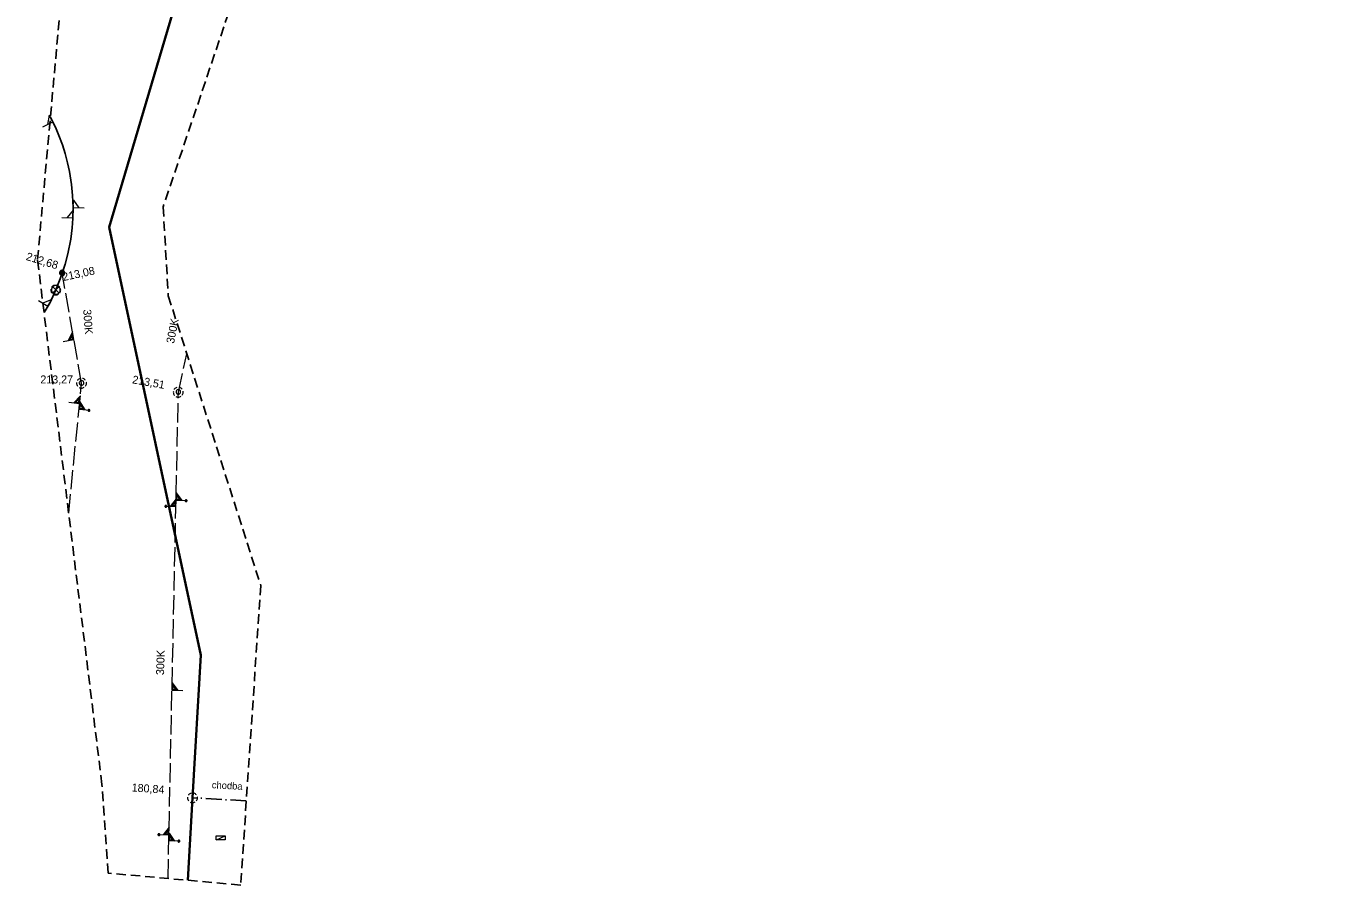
# Model space of a CAD drawing. Extents: x -744446 to -743929, y -1041261 to -1040599.
# Drawn here: x -744446.3 to -744316.9, y -1041260.9 to -1041175.1 of the extents above; entities that cross this region are included whole.
import ezdxf

# ---------------------------------------------------------------- set-up
doc = ezdxf.new("R2010")
doc.units = 0
doc.header["$LTSCALE"] = 0.32
for name, pattern in [('DOT_DASHED', [7.7, 5, -1.2, 0.3, -1.2]), ('LONG_DASHED', [7.5, 6, -1.5]), ('MEDIUM_DASHED', [4.5, 3, -1.5])]:
    doc.linetypes.add(name, pattern=pattern)
for name, color, linetype, lineweight in [('1', 7, 'MEDIUM_DASHED', 25), ('18', 7, 'Continuous', 13), ('20', 7, 'LONG_DASHED', 13)]:
    doc.layers.add(name, color=color, linetype=linetype, lineweight=lineweight)

msp = doc.modelspace()

# ---------------------------------------------------------------- linework, layer by layer
at = {"layer": '1'}
msp.add_lwpolyline([(-744438.077, -1041259.731), (-744438.679, -1041250.888), (-744445.125, -1041198.426), (-744434.434, -1041080.103), (-744426.87, -1040938.41), (-744425.446, -1040859.072), (-744414.192, -1040822.094), (-744390.076, -1040771.45), (-744357.118, -1040726.434), (-744307.278, -1040693.475), (-744241.36, -1040670.967), (-743937.498, -1040598.618), (-743928.655, -1040619.519), (-744129.684, -1040665.585), (-744218.109, -1040687.29), (-744311.358, -1040718.641), (-744361.198, -1040777.323), (-744391.745, -1040864.141), (-744411.355, -1041059.185), (-744416.379, -1041145.154), (-744432.569, -1041193.163), (-744432.047, -1041202.053), (-744422.803, -1041230.992), (-744424.813, -1041260.936)], close=True, dxfattribs=at)
at = {"layer": '18'}
for p, q in [((-744442.984, -1041201.759), (-744443.602, -1041201.141)), ((-744443.602, -1041201.759), (-744442.985, -1041201.142)), ((-744427.244, -1041256.421), (-744426.37, -1041256.009))]:
    msp.add_line(p, q, dxfattribs=at)
at = {"layer": '18', "linetype": 'DOT_DASHED', "lineweight": 25}
msp.add_line((-744424.248, -1041252.521), (-744429.62, -1041252.21), dxfattribs=at)
at = {"layer": '18'}
for points in [[(-744444.601, -1041185.157), (-744443.607, -1041184.656), (-744443.949, -1041183.978), (-744444.136, -1041184.924)], [(-744440.468, -1041193.273), (-744441.565, -1041193.244), (-744441.545, -1041192.471), (-744440.988, -1041193.259)], [(-744442.696, -1041194.214), (-744441.583, -1041194.243), (-744441.563, -1041193.483), (-744442.176, -1041194.228)], [(-744443.445, -1041200.988), (-744443.516, -1041201.016), (-744443.583, -1041201.055), (-744443.643, -1041201.103), (-744443.694, -1041201.16), (-744443.718, -1041201.194)], [(-744442.904, -1041201.171), (-744442.954, -1041201.113), (-744443.012, -1041201.063), (-744443.077, -1041201.022), (-744443.148, -1041200.993), (-744443.197, -1041200.979)], [(-744445.036, -1041202.494), (-744444.082, -1041203.068), (-744443.691, -1041202.416), (-744444.591, -1041202.763)], [(-744443.79, -1041201.38), (-744443.796, -1041201.457), (-744443.791, -1041201.534), (-744443.774, -1041201.609), (-744443.745, -1041201.68), (-744443.705, -1041201.746), (-744443.689, -1041201.768)], [(-744443.532, -1041201.897), (-744443.462, -1041201.928), (-744443.387, -1041201.947), (-744443.311, -1041201.954), (-744443.234, -1041201.949), (-744443.159, -1041201.932), (-744443.087, -1041201.904), (-744443.027, -1041201.869)], [(-744442.909, -1041201.757), (-744442.868, -1041201.692), (-744442.837, -1041201.622), (-744442.818, -1041201.547), (-744442.81, -1041201.471), (-744442.815, -1041201.394), (-744442.821, -1041201.359)], [(-744442.565, -1041206.597), (-744441.486, -1041206.406), (-744441.62, -1041205.647), (-744442.055, -1041206.507)], [(-744441.948, -1041206.436), (-744441.538, -1041206.364), (-744441.636, -1041205.807), (-744441.949, -1041206.436)], [(-744441.873, -1041206.375), (-744441.587, -1041206.324), (-744441.651, -1041205.959), (-744441.873, -1041206.376)], [(-744441.217, -1041210.69), (-744441.223, -1041210.767), (-744441.218, -1041210.844), (-744441.201, -1041210.919), (-744441.172, -1041210.99), (-744441.132, -1041211.056), (-744441.116, -1041211.078)], [(-744440.872, -1041210.298), (-744440.943, -1041210.326), (-744441.01, -1041210.365), (-744441.07, -1041210.413), (-744441.121, -1041210.47), (-744441.145, -1041210.504)], [(-744440.959, -1041211.207), (-744440.889, -1041211.238), (-744440.814, -1041211.257), (-744440.738, -1041211.264), (-744440.661, -1041211.259), (-744440.586, -1041211.242), (-744440.514, -1041211.214), (-744440.454, -1041211.179)], [(-744440.331, -1041210.481), (-744440.381, -1041210.423), (-744440.439, -1041210.373), (-744440.504, -1041210.332), (-744440.575, -1041210.303), (-744440.624, -1041210.289)], [(-744440.336, -1041211.067), (-744440.295, -1041211.002), (-744440.264, -1041210.932), (-744440.245, -1041210.857), (-744440.237, -1041210.781), (-744440.242, -1041210.704), (-744440.248, -1041210.669)], [(-744431.198, -1041211.2), (-744431.269, -1041211.228), (-744431.336, -1041211.267), (-744431.396, -1041211.315), (-744431.447, -1041211.372), (-744431.471, -1041211.406)], [(-744430.657, -1041211.383), (-744430.707, -1041211.325), (-744430.765, -1041211.275), (-744430.83, -1041211.234), (-744430.901, -1041211.205), (-744430.95, -1041211.191)], [(-744442.008, -1041212.686), (-744440.918, -1041212.795), (-744440.841, -1041212.028), (-744441.493, -1041212.738)], [(-744441.37, -1041212.699), (-744440.956, -1041212.74), (-744440.9, -1041212.177), (-744441.371, -1041212.698)], [(-744441.282, -1041212.66), (-744440.993, -1041212.689), (-744440.956, -1041212.32), (-744441.282, -1041212.661)], [(-744439.885, -1041213.504), (-744440.975, -1041213.396), (-744440.899, -1041212.63), (-744440.4, -1041213.453)], [(-744440.512, -1041213.392), (-744440.926, -1041213.351), (-744440.87, -1041212.787), (-744440.511, -1041213.392)], [(-744431.543, -1041211.592), (-744431.549, -1041211.669), (-744431.544, -1041211.746), (-744431.527, -1041211.821), (-744431.498, -1041211.892), (-744431.458, -1041211.958), (-744431.442, -1041211.98)], [(-744431.285, -1041212.109), (-744431.215, -1041212.14), (-744431.14, -1041212.159), (-744431.064, -1041212.166), (-744430.987, -1041212.161), (-744430.912, -1041212.144), (-744430.84, -1041212.116), (-744430.78, -1041212.081)], [(-744430.662, -1041211.969), (-744430.621, -1041211.904), (-744430.59, -1041211.834), (-744430.571, -1041211.759), (-744430.563, -1041211.683), (-744430.568, -1041211.606), (-744430.574, -1041211.571)], [(-744440.591, -1041213.337), (-744440.882, -1041213.308), (-744440.845, -1041212.938), (-744440.591, -1041213.338)], [(-744430.175, -1041222.525), (-744431.27, -1041222.502), (-744431.254, -1041221.732), (-744430.692, -1041222.514)], [(-744430.809, -1041222.461), (-744431.225, -1041222.453), (-744431.213, -1041221.887), (-744430.808, -1041222.461)], [(-744432.384, -1041223.076), (-744431.289, -1041223.099), (-744431.273, -1041222.329), (-744431.867, -1041223.087)], [(-744431.747, -1041223.039), (-744431.331, -1041223.048), (-744431.319, -1041222.482), (-744431.749, -1041223.039)], [(-744431.663, -1041222.993), (-744431.371, -1041223), (-744431.363, -1041222.629), (-744431.663, -1041222.994)], [(-744430.892, -1041222.413), (-744431.184, -1041222.406), (-744431.176, -1041222.034), (-744430.892, -1041222.414)], [(-744430.583, -1041241.505), (-744431.679, -1041241.481), (-744431.663, -1041240.712), (-744431.101, -1041241.494)], [(-744431.218, -1041241.441), (-744431.634, -1041241.432), (-744431.622, -1041240.867), (-744431.217, -1041241.441)], [(-744431.301, -1041241.393), (-744431.592, -1041241.386), (-744431.584, -1041241.014), (-744431.301, -1041241.394)], [(-744430.118, -1041252.139), (-744430.124, -1041252.216), (-744430.119, -1041252.293), (-744430.102, -1041252.368), (-744430.073, -1041252.439), (-744430.032, -1041252.505), (-744430.017, -1041252.527)], [(-744429.773, -1041251.747), (-744429.844, -1041251.775), (-744429.911, -1041251.814), (-744429.971, -1041251.862), (-744430.022, -1041251.919), (-744430.046, -1041251.953)], [(-744429.86, -1041252.656), (-744429.79, -1041252.687), (-744429.715, -1041252.706), (-744429.639, -1041252.713), (-744429.562, -1041252.708), (-744429.487, -1041252.691), (-744429.415, -1041252.663), (-744429.355, -1041252.628)], [(-744429.232, -1041251.93), (-744429.282, -1041251.872), (-744429.34, -1041251.822), (-744429.405, -1041251.781), (-744429.476, -1041251.752), (-744429.525, -1041251.738)], [(-744429.237, -1041252.516), (-744429.196, -1041252.451), (-744429.165, -1041252.381), (-744429.146, -1041252.306), (-744429.138, -1041252.23), (-744429.143, -1041252.153), (-744429.149, -1041252.118)], [(-744433.082, -1041255.892), (-744431.987, -1041255.915), (-744431.971, -1041255.145), (-744432.565, -1041255.903)], [(-744432.445, -1041255.855), (-744432.029, -1041255.864), (-744432.017, -1041255.298), (-744432.447, -1041255.855)], [(-744432.361, -1041255.809), (-744432.069, -1041255.816), (-744432.061, -1041255.445), (-744432.361, -1041255.81)], [(-744430.898, -1041256.541), (-744431.993, -1041256.518), (-744431.977, -1041255.748), (-744431.415, -1041256.53)], [(-744431.532, -1041256.477), (-744431.948, -1041256.469), (-744431.936, -1041255.903), (-744431.531, -1041256.477)], [(-744431.615, -1041256.429), (-744431.907, -1041256.422), (-744431.899, -1041256.05), (-744431.615, -1041256.43)]]:
    msp.add_lwpolyline(points, dxfattribs=at)
for points in [[(-744442.4, -1041199.751), (-744442.406, -1041199.695), (-744442.423, -1041199.642), (-744442.451, -1041199.593), (-744442.49, -1041199.552), (-744442.536, -1041199.52), (-744442.588, -1041199.498), (-744442.643, -1041199.487), (-744442.699, -1041199.489), (-744442.754, -1041199.502), (-744442.804, -1041199.527), (-744442.849, -1041199.562), (-744442.885, -1041199.605), (-744442.91, -1041199.655), (-744442.925, -1041199.71), (-744442.928, -1041199.766), (-744442.919, -1041199.821), (-744442.898, -1041199.874), (-744442.867, -1041199.92), (-744442.826, -1041199.959), (-744442.779, -1041199.989), (-744442.726, -1041200.008), (-744442.67, -1041200.015), (-744442.614, -1041200.011), (-744442.559, -1041199.994), (-744442.511, -1041199.967), (-744442.469, -1041199.929), (-744442.436, -1041199.884), (-744442.413, -1041199.833), (-744442.401, -1041199.778)], [(-744442.459, -1041199.754), (-744442.465, -1041199.705), (-744442.483, -1041199.659), (-744442.511, -1041199.618), (-744442.548, -1041199.585), (-744442.592, -1041199.563), (-744442.64, -1041199.551), (-744442.689, -1041199.551), (-744442.737, -1041199.563), (-744442.781, -1041199.586), (-744442.818, -1041199.619), (-744442.846, -1041199.66), (-744442.863, -1041199.707), (-744442.869, -1041199.756), (-744442.862, -1041199.805), (-744442.844, -1041199.851), (-744442.816, -1041199.891), (-744442.779, -1041199.924), (-744442.735, -1041199.946), (-744442.686, -1041199.958), (-744442.637, -1041199.957), (-744442.589, -1041199.945), (-744442.546, -1041199.921), (-744442.509, -1041199.888), (-744442.481, -1041199.847), (-744442.465, -1041199.8)], [(-744442.518, -1041199.758), (-744442.524, -1041199.716), (-744442.541, -1041199.678), (-744442.569, -1041199.647), (-744442.603, -1041199.624), (-744442.644, -1041199.613), (-744442.686, -1041199.613), (-744442.726, -1041199.625), (-744442.761, -1041199.648), (-744442.788, -1041199.68), (-744442.804, -1041199.718), (-744442.809, -1041199.759), (-744442.804, -1041199.801), (-744442.786, -1041199.838), (-744442.758, -1041199.87), (-744442.722, -1041199.892), (-744442.682, -1041199.903), (-744442.64, -1041199.902), (-744442.6, -1041199.889), (-744442.566, -1041199.866), (-744442.539, -1041199.833), (-744442.523, -1041199.795)], [(-744442.857, -1041201.451), (-744442.859, -1041201.405), (-744442.866, -1041201.36), (-744442.878, -1041201.316), (-744442.894, -1041201.273), (-744442.915, -1041201.232), (-744442.94, -1041201.194), (-744442.969, -1041201.158), (-744443.001, -1041201.126), (-744443.037, -1041201.097), (-744443.075, -1041201.072), (-744443.116, -1041201.052), (-744443.159, -1041201.035), (-744443.203, -1041201.023), (-744443.248, -1041201.016), (-744443.294, -1041201.014), (-744443.34, -1041201.016), (-744443.385, -1041201.023), (-744443.429, -1041201.035), (-744443.472, -1041201.052), (-744443.513, -1041201.072), (-744443.551, -1041201.097), (-744443.587, -1041201.126), (-744443.619, -1041201.158), (-744443.648, -1041201.194), (-744443.673, -1041201.233), (-744443.694, -1041201.273), (-744443.71, -1041201.316), (-744443.722, -1041201.36), (-744443.729, -1041201.405), (-744443.732, -1041201.451), (-744443.729, -1041201.497), (-744443.722, -1041201.542), (-744443.71, -1041201.586), (-744443.694, -1041201.629), (-744443.673, -1041201.67), (-744443.648, -1041201.708), (-744443.619, -1041201.744), (-744443.587, -1041201.776), (-744443.551, -1041201.805), (-744443.513, -1041201.83), (-744443.472, -1041201.851), (-744443.429, -1041201.867), (-744443.385, -1041201.879), (-744443.34, -1041201.886), (-744443.294, -1041201.889), (-744443.248, -1041201.886), (-744443.203, -1041201.879), (-744443.159, -1041201.867), (-744443.116, -1041201.851), (-744443.075, -1041201.83), (-744443.037, -1041201.805), (-744443.001, -1041201.776), (-744442.969, -1041201.744), (-744442.94, -1041201.708), (-744442.915, -1041201.67), (-744442.894, -1041201.629), (-744442.878, -1041201.586), (-744442.866, -1041201.542), (-744442.859, -1041201.497)], [(-744440.488, -1041210.75), (-744440.494, -1041210.698), (-744440.512, -1041210.648), (-744440.54, -1041210.604), (-744440.578, -1041210.567), (-744440.623, -1041210.54), (-744440.673, -1041210.524), (-744440.725, -1041210.519), (-744440.777, -1041210.526), (-744440.826, -1041210.545), (-744440.87, -1041210.575), (-744440.905, -1041210.614), (-744440.931, -1041210.659), (-744440.946, -1041210.71), (-744440.949, -1041210.762), (-744440.941, -1041210.814), (-744440.92, -1041210.862), (-744440.89, -1041210.905), (-744440.85, -1041210.94), (-744440.804, -1041210.964), (-744440.753, -1041210.978), (-744440.701, -1041210.98), (-744440.649, -1041210.97), (-744440.601, -1041210.948), (-744440.559, -1041210.916), (-744440.526, -1041210.876), (-744440.502, -1041210.829), (-744440.49, -1041210.778)], [(-744430.814, -1041211.652), (-744430.82, -1041211.6), (-744430.838, -1041211.55), (-744430.866, -1041211.506), (-744430.904, -1041211.469), (-744430.949, -1041211.442), (-744430.999, -1041211.426), (-744431.051, -1041211.421), (-744431.103, -1041211.428), (-744431.152, -1041211.447), (-744431.196, -1041211.477), (-744431.231, -1041211.516), (-744431.257, -1041211.561), (-744431.272, -1041211.612), (-744431.275, -1041211.664), (-744431.267, -1041211.716), (-744431.246, -1041211.764), (-744431.216, -1041211.807), (-744431.176, -1041211.842), (-744431.13, -1041211.866), (-744431.079, -1041211.88), (-744431.027, -1041211.882), (-744430.975, -1041211.872), (-744430.927, -1041211.85), (-744430.885, -1041211.818), (-744430.852, -1041211.778), (-744430.828, -1041211.731), (-744430.816, -1041211.68)], [(-744439.97, -1041213.401), (-744440.003, -1041213.404), (-744440.034, -1041213.418), (-744440.057, -1041213.442), (-744440.07, -1041213.473), (-744440.073, -1041213.506), (-744440.063, -1041213.538), (-744440.042, -1041213.565), (-744440.014, -1041213.583), (-744439.981, -1041213.589), (-744439.949, -1041213.584), (-744439.919, -1041213.568), (-744439.897, -1041213.542), (-744439.886, -1041213.511), (-744439.886, -1041213.477), (-744439.898, -1041213.446), (-744439.92, -1041213.421), (-744439.95, -1041213.405)], [(-744439.973, -1041213.428), (-744440.002, -1041213.431), (-744440.026, -1041213.445), (-744440.042, -1041213.469), (-744440.047, -1041213.496), (-744440.041, -1041213.524), (-744440.023, -1041213.546), (-744439.998, -1041213.559), (-744439.971, -1041213.561), (-744439.944, -1041213.552), (-744439.924, -1041213.532), (-744439.914, -1041213.505), (-744439.915, -1041213.477), (-744439.929, -1041213.452), (-744439.95, -1041213.435)], [(-744432.288, -1041222.983), (-744432.321, -1041222.989), (-744432.35, -1041223.005), (-744432.372, -1041223.03), (-744432.382, -1041223.062), (-744432.382, -1041223.095), (-744432.37, -1041223.126), (-744432.347, -1041223.152), (-744432.318, -1041223.168), (-744432.285, -1041223.172), (-744432.252, -1041223.164), (-744432.224, -1041223.146), (-744432.205, -1041223.119), (-744432.196, -1041223.086), (-744432.198, -1041223.053), (-744432.213, -1041223.023), (-744432.237, -1041222.999), (-744432.268, -1041222.986)], [(-744432.286, -1041223.01), (-744432.314, -1041223.016), (-744432.338, -1041223.032), (-744432.352, -1041223.056), (-744432.355, -1041223.085), (-744432.346, -1041223.111), (-744432.328, -1041223.132), (-744432.302, -1041223.144), (-744432.273, -1041223.144), (-744432.248, -1041223.131), (-744432.229, -1041223.11), (-744432.221, -1041223.083), (-744432.224, -1041223.056), (-744432.24, -1041223.031), (-744432.263, -1041223.015)], [(-744430.267, -1041222.429), (-744430.3, -1041222.434), (-744430.33, -1041222.451), (-744430.351, -1041222.476), (-744430.362, -1041222.508), (-744430.362, -1041222.541), (-744430.349, -1041222.572), (-744430.327, -1041222.598), (-744430.297, -1041222.613), (-744430.264, -1041222.617), (-744430.232, -1041222.61), (-744430.204, -1041222.591), (-744430.184, -1041222.564), (-744430.175, -1041222.532), (-744430.178, -1041222.498), (-744430.192, -1041222.468), (-744430.217, -1041222.445), (-744430.247, -1041222.431)], [(-744430.269, -1041222.456), (-744430.297, -1041222.461), (-744430.32, -1041222.477), (-744430.334, -1041222.501), (-744430.337, -1041222.529), (-744430.329, -1041222.557), (-744430.309, -1041222.577), (-744430.284, -1041222.589), (-744430.256, -1041222.588), (-744430.23, -1041222.577), (-744430.212, -1041222.555), (-744430.203, -1041222.528), (-744430.207, -1041222.5), (-744430.222, -1041222.476), (-744430.245, -1041222.46)], [(-744432.986, -1041255.799), (-744433.019, -1041255.805), (-744433.048, -1041255.821), (-744433.07, -1041255.846), (-744433.08, -1041255.878), (-744433.08, -1041255.911), (-744433.068, -1041255.942), (-744433.045, -1041255.968), (-744433.016, -1041255.984), (-744432.983, -1041255.988), (-744432.95, -1041255.98), (-744432.922, -1041255.962), (-744432.903, -1041255.935), (-744432.894, -1041255.902), (-744432.896, -1041255.869), (-744432.911, -1041255.839), (-744432.935, -1041255.815), (-744432.966, -1041255.802)], [(-744432.984, -1041255.826), (-744433.012, -1041255.832), (-744433.036, -1041255.848), (-744433.05, -1041255.872), (-744433.053, -1041255.901), (-744433.044, -1041255.927), (-744433.026, -1041255.948), (-744433, -1041255.96), (-744432.971, -1041255.96), (-744432.946, -1041255.947), (-744432.927, -1041255.926), (-744432.919, -1041255.899), (-744432.922, -1041255.872), (-744432.938, -1041255.847), (-744432.961, -1041255.831)], [(-744430.99, -1041256.445), (-744431.023, -1041256.45), (-744431.053, -1041256.467), (-744431.074, -1041256.492), (-744431.085, -1041256.524), (-744431.085, -1041256.557), (-744431.072, -1041256.588), (-744431.05, -1041256.614), (-744431.02, -1041256.629), (-744430.987, -1041256.633), (-744430.955, -1041256.626), (-744430.927, -1041256.607), (-744430.907, -1041256.58), (-744430.898, -1041256.548), (-744430.901, -1041256.514), (-744430.915, -1041256.484), (-744430.94, -1041256.461), (-744430.97, -1041256.447)], [(-744430.992, -1041256.472), (-744431.02, -1041256.477), (-744431.043, -1041256.493), (-744431.057, -1041256.517), (-744431.06, -1041256.545), (-744431.052, -1041256.573), (-744431.032, -1041256.593), (-744431.007, -1041256.605), (-744430.979, -1041256.604), (-744430.953, -1041256.593), (-744430.935, -1041256.571), (-744430.926, -1041256.544), (-744430.93, -1041256.516), (-744430.945, -1041256.492), (-744430.968, -1041256.476)], [(-744427.248, -1041256.009), (-744426.374, -1041256.009), (-744426.374, -1041256.421), (-744427.248, -1041256.421)]]:
    msp.add_lwpolyline(points, close=True, dxfattribs=at)
at = {"layer": '20'}
for p, q in [((-744440.719, -1041210.761), (-744442.664, -1041199.764)), ((-744431.045, -1041211.663), (-744430.194, -1041207.856)), ((-744442.011, -1041223.766), (-744440.719, -1041210.761)), ((-744432.078, -1041260.276), (-744431.045, -1041211.663))]:
    msp.add_line(p, q, dxfattribs=at)
at = {"layer": '20', "linetype": 'Continuous', "lineweight": 35}
msp.add_line((-744430.103, -1041260.455), (-744429.62, -1041252.21), dxfattribs=at)
msp.add_lwpolyline([(-744429.62, -1041252.21), (-744428.789, -1041237.94), (-744437.959, -1041195.193), (-744423.3, -1041145.69), (-744417.879, -1041053.98), (-744409.949, -1040917.67), (-744407.76, -1040880.01), (-744407.219, -1040869.23), (-744404.395, -1040847.829), (-744400.25, -1040827.35), (-744393.491, -1040807.621), (-744384.879, -1040787.9), (-744372.238, -1040768.547), (-744361.26, -1040752.62), (-744345.317, -1040736.555), (-744330.739, -1040723.14), (-744312.333, -1040710.859), (-744294.67, -1040700.75), (-744274.728, -1040692.583), (-744254.699, -1040686.49), (-744133.87, -1040657.39), (-743953.289, -1040613.85), (-743946.017, -1040612.141)], dxfattribs=at)
at = {"layer": '20', "lineweight": 25}
for points in [[(-744442.664, -1041199.764), (-744442.366, -1041198.886), (-744442.103, -1041197.853), (-744441.804, -1041196.367), (-744441.65, -1041195.259), (-744441.592, -1041194.325), (-744441.563, -1041193.216), (-744441.621, -1041192.02), (-744441.724, -1041190.926), (-744441.928, -1041189.613), (-744442.132, -1041188.767), (-744442.366, -1041187.819), (-744442.644, -1041186.958), (-744443.007, -1041186.019), (-744443.345, -1041185.193), (-744443.84, -1041184.21)], [(-744443.292, -1041201.451), (-744442.851, -1041200.358), (-744442.664, -1041199.764)], [(-744444.476, -1041203.709), (-744443.875, -1041202.71), (-744443.292, -1041201.451)]]:
    msp.add_lwpolyline(points, dxfattribs=at)

# ---------------------------------------------------------------- texts
at = {"layer": '1'}
for s, height, rotation, p in [('212,68', 0.8, 343, (-744446.341, -1041198.441)), ('213,08', 0.8, 12, (-744442.542, -1041200.567)), ('300K', 0.8, 274, (-744440.561, -1041203.42)), ('300K', 0.8, 79, (-744431.481, -1041206.855)), ('213,51', 0.8, 350, (-744435.699, -1041210.779)), ('300K', 0.8, 88, (-744432.482, -1041239.959)), ('180,84', 0.8, 356, (-744435.734, -1041251.567)), ('chodba', 0.7, 357, (-744427.711, -1041251.258))]:
    msp.add_text(s, height=height, rotation=rotation, dxfattribs=at).set_placement(p)
msp.add_text('213,27', height=0.8, dxfattribs=at).set_placement((-744444.845, -1041210.8))

doc.saveas('drawing.dxf')
